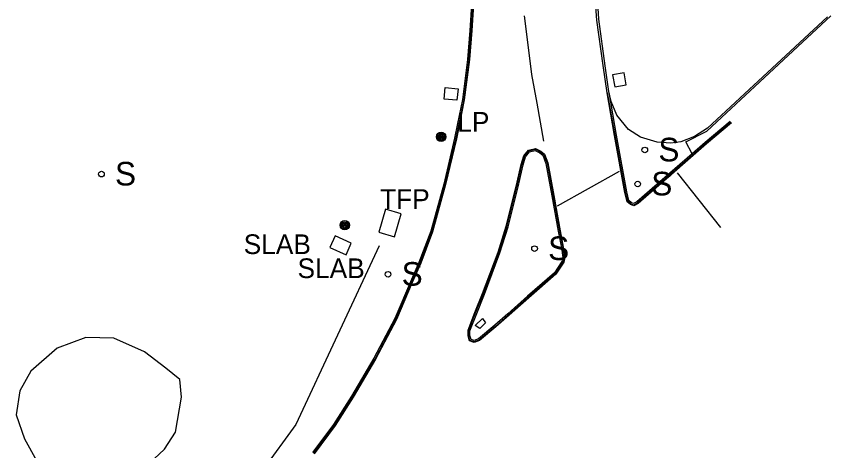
# Model space of a CAD drawing. Extents: x 368532 to 392481, y 10654822 to 10676899.
# Drawn here: x 375151.5 to 375358.7, y 10671645.4 to 10671755.9 of the extents above; entities that cross this region are included whole.
import ezdxf

# ---------------------------------------------------------------- set-up
doc = ezdxf.new("R2010")
doc.units = 0
for name, color, linetype in [('p_dtm sidewalk', 7, 'Continuous'), ('p_dtm slab', 7, 'Continuous'), ('p_dtm stock pile', 7, 'Continuous'), ('p_road - paved curb', 7, 'Continuous'), ('p_road guard rails', 7, 'Continuous'), ('p_road paint stripe', 7, 'Continuous'), ('p_structure constr area', 7, 'Continuous'), ('p_structure sign', 7, 'Continuous'), ('p_structure unidentified', 7, 'Continuous'), ('p_utility general pole', 7, 'Continuous')]:
    doc.layers.add(name, color=color, linetype=linetype)

msp = doc.modelspace()

# ---------------------------------------------------------------- linework, layer by layer
at = {"layer": 'p_dtm sidewalk'}
for p, q in [((375332.24, 10671731.3), (375358.75, 10671755.95)), ((375327.2, 10671726.63), (375332.24, 10671731.3)), ((375321.84, 10671723.95), (375327.2, 10671726.63)), ((375323.45, 10671720.85), (375321.84, 10671723.95))]:
    msp.add_line(p, q, dxfattribs=at)
at = {"layer": 'p_dtm slab'}
for p, q in [((375245.45, 10671706.83), (375243.71, 10671700.95)), ((375249.46, 10671705.64), (375245.45, 10671706.83)), ((375247.72, 10671699.77), (375249.46, 10671705.64)), ((375243.71, 10671700.95), (375247.72, 10671699.77)), ((375232.59, 10671700.06), (375231.26, 10671697.11)), ((375236.73, 10671698.2), (375232.59, 10671700.06)), ((375231.26, 10671697.11), (375235.4, 10671695.25)), ((375235.4, 10671695.25), (375236.73, 10671698.2))]:
    msp.add_line(p, q, dxfattribs=at)
at = {"layer": 'p_dtm stock pile'}
for p, q in [((375169.21, 10671674.2), (375161.86, 10671671.47)), ((375176.32, 10671673.98), (375169.21, 10671674.2)), ((375184.07, 10671670.53), (375176.32, 10671673.98)), ((375161.86, 10671671.47), (375155.14, 10671665.6)), ((375189.57, 10671666.36), (375184.07, 10671670.53)), ((375155.14, 10671665.6), (375152.41, 10671660.66)), ((375193.09, 10671663.49), (375189.57, 10671666.36)), ((375193.5, 10671659), (375193.09, 10671663.49)), ((375152.41, 10671660.66), (375151.47, 10671654.52)), ((375191.98, 10671650.1), (375193.5, 10671659)), ((375151.47, 10671654.52), (375153.57, 10671648.41)), ((375189.16, 10671645.76), (375191.98, 10671650.1)), ((375153.57, 10671648.41), (375156.63, 10671642.92)), ((375183.98, 10671640.97), (375189.16, 10671645.76))]:
    msp.add_line(p, q, dxfattribs=at)
at = {"layer": 'p_road - paved curb'}
for p, q in [((375299.26, 10671754.89), (375298.25, 10671767.88)), ((375267.31, 10671758.83), (375266.92, 10671752.27)), ((375267.66, 10671758.82), (375267.27, 10671752.24)), ((375267.81, 10671758.82), (375267.42, 10671752.23)), ((375300.81, 10671743.36), (375299.26, 10671754.89)), ((375266.92, 10671752.27), (375266.31, 10671744.89)), ((375267.27, 10671752.24), (375266.66, 10671744.86)), ((375267.42, 10671752.23), (375266.81, 10671744.84)), ((375266.31, 10671744.89), (375265, 10671734.67)), ((375266.66, 10671744.86), (375265.34, 10671734.61)), ((375266.81, 10671744.84), (375265.49, 10671734.59)), ((375301.83, 10671736.41), (375300.81, 10671743.36)), ((375303.73, 10671725.54), (375301.83, 10671736.41)), ((375303.88, 10671725.57), (375301.98, 10671736.44)), ((375304.22, 10671725.63), (375302.32, 10671736.5)), ((375265, 10671734.67), (375263.74, 10671728.58)), ((375265.34, 10671734.61), (375264.08, 10671728.51)), ((375265.49, 10671734.59), (375264.23, 10671728.48)), ((375263.74, 10671728.58), (375262.99, 10671724.85)), ((375264.08, 10671728.51), (375263.33, 10671724.77)), ((375264.23, 10671728.48), (375263.48, 10671724.74)), ((375333.19, 10671729.11), (375326.82, 10671723.77)), ((375333.41, 10671728.84), (375327.04, 10671723.5)), ((375333.51, 10671728.73), (375327.14, 10671723.39)), ((375306.34, 10671711.1), (375303.73, 10671725.54)), ((375306.49, 10671711.13), (375303.88, 10671725.57)), ((375306.83, 10671711.21), (375304.22, 10671725.63)), ((375262.99, 10671724.85), (375260.25, 10671713.21)), ((375263.33, 10671724.77), (375260.58, 10671713.13)), ((375263.48, 10671724.74), (375260.73, 10671713.09)), ((375326.82, 10671723.77), (375323.45, 10671720.85)), ((375327.04, 10671723.5), (375323.68, 10671720.58)), ((375327.14, 10671723.39), (375323.78, 10671720.47)), ((375280.64, 10671720.4), (375281.83, 10671721.81)), ((375280.78, 10671720.33), (375281.91, 10671721.68)), ((375281.09, 10671720.16), (375282.11, 10671721.36)), ((375281.83, 10671721.81), (375283.62, 10671722.23)), ((375281.91, 10671721.68), (375283.6, 10671722.07)), ((375282.11, 10671721.36), (375283.56, 10671721.7)), ((375283.56, 10671721.7), (375284.68, 10671721.13)), ((375283.6, 10671722.07), (375284.87, 10671721.42)), ((375283.62, 10671722.23), (375284.95, 10671721.55)), ((375284.87, 10671721.42), (375285.76, 10671720.74)), ((375284.95, 10671721.55), (375285.89, 10671720.83)), ((375280, 10671718.18), (375280.64, 10671720.4)), ((375280.15, 10671718.14), (375280.78, 10671720.33)), ((375280.48, 10671718.05), (375281.09, 10671720.16)), ((375284.68, 10671721.13), (375285.47, 10671720.52)), ((375285.47, 10671720.52), (375286.26, 10671718.46)), ((375285.76, 10671720.74), (375286.59, 10671718.56)), ((375285.89, 10671720.83), (375286.74, 10671718.6)), ((375323.45, 10671720.85), (375317.2, 10671715.45)), ((375323.68, 10671720.58), (375317.43, 10671715.18)), ((375323.78, 10671720.47), (375317.53, 10671715.07)), ((375278.72, 10671712.58), (375280, 10671718.18)), ((375278.87, 10671712.54), (375280.15, 10671718.14)), ((375279.21, 10671712.46), (375280.48, 10671718.05)), ((375286.26, 10671718.46), (375287.79, 10671710.18)), ((375286.59, 10671718.56), (375288.13, 10671710.24)), ((375286.74, 10671718.6), (375288.28, 10671710.27)), ((375317.2, 10671715.45), (375311.34, 10671710.37)), ((375317.43, 10671715.18), (375311.57, 10671710.1)), ((375317.53, 10671715.07), (375311.67, 10671709.99)), ((375260.25, 10671713.21), (375256.95, 10671701.22)), ((375260.58, 10671713.13), (375257.29, 10671701.11)), ((375260.73, 10671713.09), (375257.43, 10671701.06)), ((375276.15, 10671702.46), (375278.72, 10671712.58)), ((375276.29, 10671702.42), (375278.87, 10671712.54)), ((375276.63, 10671702.32), (375279.21, 10671712.46)), ((375306.96, 10671708.71), (375306.34, 10671711.1)), ((375307.09, 10671708.79), (375306.49, 10671711.13)), ((375307.4, 10671708.99), (375306.83, 10671711.21)), ((375287.79, 10671710.18), (375289.37, 10671701.26)), ((375288.13, 10671710.24), (375289.71, 10671701.32)), ((375288.28, 10671710.27), (375289.86, 10671701.35)), ((375308.01, 10671708.47), (375307.4, 10671708.99)), ((375311.34, 10671710.37), (375309.43, 10671708.7)), ((375311.57, 10671710.1), (375309.62, 10671708.41)), ((375311.67, 10671709.99), (375309.71, 10671708.29)), ((375307.75, 10671708.04), (375306.96, 10671708.71)), ((375307.83, 10671708.17), (375307.09, 10671708.79)), ((375308.6, 10671707.7), (375307.75, 10671708.04)), ((375308.59, 10671707.87), (375307.83, 10671708.17)), ((375308.57, 10671708.25), (375308.01, 10671708.47)), ((375309.43, 10671708.7), (375308.57, 10671708.25)), ((375309.62, 10671708.41), (375308.59, 10671707.87)), ((375309.71, 10671708.29), (375308.6, 10671707.7)), ((375256.95, 10671701.22), (375253.93, 10671693.29)), ((375257.29, 10671701.11), (375254.25, 10671693.16)), ((375257.43, 10671701.06), (375254.39, 10671693.1)), ((375274.1, 10671695.88), (375276.15, 10671702.46)), ((375274.24, 10671695.83), (375276.29, 10671702.42)), ((375274.57, 10671695.72), (375276.63, 10671702.32)), ((375289.37, 10671701.26), (375290.2, 10671697.03)), ((375289.71, 10671701.32), (375290.54, 10671697.09)), ((375289.86, 10671701.35), (375290.69, 10671697.12)), ((375290.2, 10671697.03), (375290.57, 10671694.53)), ((375290.54, 10671697.09), (375290.93, 10671694.52)), ((375290.69, 10671697.12), (375291.08, 10671694.51)), ((375270.13, 10671685.38), (375274.1, 10671695.88)), ((375270.27, 10671685.33), (375274.24, 10671695.83)), ((375270.6, 10671685.2), (375274.57, 10671695.72)), ((375290.57, 10671694.53), (375290.34, 10671693.54)), ((375290.93, 10671694.52), (375290.67, 10671693.4)), ((375291.08, 10671694.51), (375290.81, 10671693.34)), ((375253.93, 10671693.29), (375251.8, 10671688.37)), ((375254.25, 10671693.16), (375252.12, 10671688.23)), ((375254.39, 10671693.1), (375252.26, 10671688.17)), ((375290.34, 10671693.54), (375288.45, 10671690.62)), ((375290.67, 10671693.4), (375288.72, 10671690.39)), ((375290.81, 10671693.34), (375288.83, 10671690.29)), ((375288.45, 10671690.62), (375281.55, 10671684.69)), ((375288.72, 10671690.39), (375281.78, 10671684.42)), ((375288.83, 10671690.29), (375281.88, 10671684.31)), ((375251.8, 10671688.37), (375247.79, 10671678.99)), ((375252.12, 10671688.23), (375248.1, 10671678.83)), ((375252.26, 10671688.17), (375248.24, 10671678.77)), ((375268.19, 10671680.51), (375270.13, 10671685.38)), ((375268.33, 10671680.45), (375270.27, 10671685.33)), ((375268.66, 10671680.33), (375270.6, 10671685.2)), ((375281.55, 10671684.69), (375276.55, 10671680.21)), ((375281.78, 10671684.42), (375276.78, 10671679.95)), ((375281.88, 10671684.31), (375276.88, 10671679.84)), ((375266.45, 10671676.06), (375268.19, 10671680.51)), ((375266.59, 10671676.01), (375268.33, 10671680.45)), ((375266.92, 10671675.88), (375268.66, 10671680.33)), ((375276.55, 10671680.21), (375273.23, 10671677.29)), ((375276.78, 10671679.95), (375273.46, 10671677.02)), ((375276.88, 10671679.84), (375273.56, 10671676.91)), ((375247.79, 10671678.99), (375242.46, 10671668.92)), ((375248.1, 10671678.83), (375242.77, 10671668.75)), ((375248.24, 10671678.77), (375242.9, 10671668.68)), ((375266.45, 10671674.6), (375266.45, 10671676.06)), ((375266.59, 10671674.64), (375266.59, 10671676.01)), ((375266.93, 10671674.74), (375266.92, 10671675.88)), ((375273.23, 10671677.29), (375269.09, 10671673.84)), ((375273.46, 10671677.02), (375269.26, 10671673.53)), ((375273.56, 10671676.91), (375269.34, 10671673.4)), ((375266.82, 10671673.31), (375266.45, 10671674.6)), ((375266.94, 10671673.43), (375266.59, 10671674.64)), ((375267.23, 10671673.7), (375266.93, 10671674.74)), ((375267.98, 10671673.45), (375267.23, 10671673.7)), ((375269.09, 10671673.84), (375267.98, 10671673.45)), ((375267.99, 10671672.92), (375266.82, 10671673.31)), ((375267.99, 10671673.08), (375266.94, 10671673.43)), ((375269.26, 10671673.53), (375267.99, 10671673.08)), ((375269.34, 10671673.4), (375267.99, 10671672.92)), ((375242.46, 10671668.92), (375236.75, 10671659.28)), ((375242.77, 10671668.75), (375237.05, 10671659.1)), ((375242.9, 10671668.68), (375237.18, 10671659.02)), ((375236.75, 10671659.28), (375232.19, 10671652.07)), ((375237.05, 10671659.1), (375232.48, 10671651.88)), ((375237.18, 10671659.02), (375232.6, 10671651.79)), ((375232.19, 10671652.07), (375226.87, 10671644.93)), ((375232.48, 10671651.88), (375227.15, 10671644.72)), ((375232.6, 10671651.79), (375227.27, 10671644.63))]:
    msp.add_line(p, q, dxfattribs=at)
at = {"layer": 'p_road guard rails'}
for p, q in [((375299.75, 10671755.17), (375297.73, 10671786.11)), ((375301.38, 10671743.24), (375299.75, 10671755.17)), ((375357.95, 10671755.76), (375327.37, 10671727.4)), ((375302.26, 10671736.77), (375301.38, 10671743.24)), ((375302.88, 10671734.21), (375302.26, 10671736.77)), ((375304.34, 10671730.75), (375302.88, 10671734.21)), ((375307.29, 10671727.07), (375304.34, 10671730.75)), ((375310.34, 10671725.14), (375307.29, 10671727.07)), ((375327.37, 10671727.4), (375324.08, 10671725.29)), ((375314.62, 10671723.85), (375310.34, 10671725.14)), ((375318.08, 10671723.58), (375314.62, 10671723.85)), ((375320.56, 10671723.95), (375318.08, 10671723.58)), ((375324.08, 10671725.29), (375320.56, 10671723.95))]:
    msp.add_line(p, q, dxfattribs=at)
at = {"layer": 'p_road paint stripe'}
for p, q in [((375281.77, 10671748.6), (375280.8, 10671756.01)), ((375282.68, 10671741.04), (375281.77, 10671748.6)), ((375284.02, 10671733.79), (375282.68, 10671741.04)), ((375285.73, 10671724.15), (375284.02, 10671733.79)), ((375289.24, 10671707.67), (375304.97, 10671716.46)), ((375319.64, 10671716.07), (375330.68, 10671702.17))]:
    msp.add_line(p, q, dxfattribs=at)
at = {"layer": 'p_structure constr area'}
for p, q in [((375243.84, 10671697.46), (375222.64, 10671652.08)), ((375222.64, 10671652.08), (375199.41, 10671620.35))]:
    msp.add_line(p, q, dxfattribs=at)
at = {"layer": 'p_structure sign'}
for centre in [(375311.43, 10671721.87), (375173.14, 10671715.74), (375309.63, 10671713.22), (375283.37, 10671696.79), (375246.09, 10671690.26)]:
    msp.add_circle(centre, 0.713, dxfattribs=at)
at = {"layer": 'p_structure unidentified'}
for p, q in [((375306.15, 10671741.48), (375303.25, 10671740.98)), ((375303.25, 10671740.98), (375303.77, 10671737.94)), ((375306.67, 10671738.44), (375306.15, 10671741.48)), ((375303.77, 10671737.94), (375306.67, 10671738.44)), ((375260.35, 10671734.82), (375260.61, 10671737.73)), ((375260.61, 10671737.73), (375263.9, 10671737.43)), ((375263.9, 10671737.43), (375263.63, 10671734.52)), ((375263.63, 10671734.52), (375260.35, 10671734.82)), ((375268.27, 10671677.21), (375270.15, 10671679.04)), ((375270.91, 10671677.89), (375269.45, 10671676.44)), ((375270.15, 10671679.04), (375270.91, 10671677.89)), ((375269.45, 10671676.44), (375268.27, 10671677.21))]:
    msp.add_line(p, q, dxfattribs=at)
at = {"layer": 'p_utility general pole'}
for centre, radius in [((375259.59, 10671725.23), 1.19), ((375259.59, 10671725.23), 0.901), ((375259.59, 10671725.23), 0.608), ((375259.59, 10671725.23), 0.337), ((375259.59, 10671725.23), 0.12), ((375235.08, 10671702.72), 1.19), ((375235.08, 10671702.72), 0.901), ((375235.08, 10671702.72), 0.608), ((375235.08, 10671702.72), 0.337), ((375235.08, 10671702.72), 0.12)]:
    msp.add_circle(centre, radius, dxfattribs=at)

# ---------------------------------------------------------------- texts
at = {"layer": 'p_dtm slab'}
for p in [(375207.49, 10671695.41), (375221.19, 10671689.3)]:
    msp.add_text(' SLAB', height=5, dxfattribs=at).set_placement(p)
at = {"layer": 'p_structure sign'}
for p in [(375314.89, 10671718.97), (375176.6, 10671712.84), (375313.09, 10671710.32), (375286.83, 10671693.89), (375249.55, 10671687.36)]:
    msp.add_text('S', height=6, dxfattribs=at).set_placement(p)
at = {"layer": 'p_utility general pole'}
for s, p in [('LP', (375263.71, 10671726.52)), ('TFP', (375244.06, 10671706.9))]:
    msp.add_text(s, height=5, dxfattribs=at).set_placement(p)

doc.saveas('drawing.dxf')
